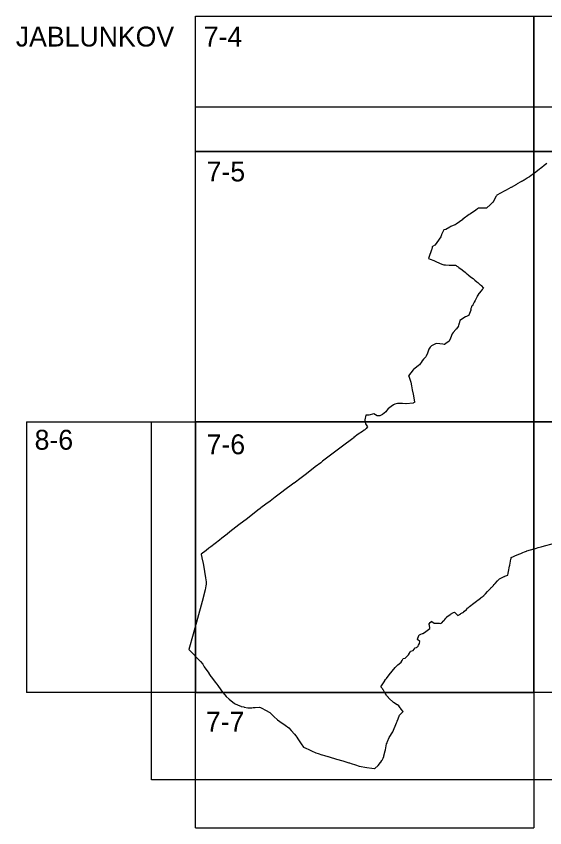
# Model space of a CAD drawing. Extents: x -449577 to -425530, y -1150048 to -1121091.
# Drawn here: x -442174.2 to -441930, y -1122269.2 to -1121894.2 of the extents above; entities that cross this region are included whole.
import ezdxf

# ---------------------------------------------------------------- set-up
doc = ezdxf.new("R2010")
doc.units = 0
for name, color, linetype in [('Vrstva 1', 7, 'Continuous'), ('Vrstva 10', 7, 'Continuous'), ('Vrstva 4', 7, 'Continuous')]:
    doc.layers.add(name, color=color, linetype=linetype)

msp = doc.modelspace()

# ---------------------------------------------------------------- linework, layer by layer
at = {"layer": 'Vrstva 1'}
for points in [[(-441928.97, -1121962.23), (-441930.18, -1121963.19), (-441930.18, -1121963.19), (-441931.33, -1121964.06), (-441931.9, -1121964.49), (-441932.48, -1121964.93), (-441932.64, -1121965.05), (-441934.77, -1121966.69), (-441935.84, -1121967.51), (-441936.31, -1121967.85), (-441937.07, -1121968.36), (-441937.32, -1121968.52), (-441937.91, -1121968.91), (-441937.95, -1121968.94), (-441938.16, -1121969.08), (-441939.07, -1121969.68), (-441939.08, -1121969.68), (-441939.55, -1121969.94), (-441939.7, -1121970.02), (-441939.88, -1121970.12), (-441940.34, -1121970.37), (-441940.52, -1121970.48), (-441940.68, -1121970.57), (-441940.78, -1121970.63), (-441941.02, -1121970.77), (-441942.68, -1121971.71), (-441942.85, -1121971.8), (-441943.08, -1121971.93), (-441945.55, -1121973.33), (-441945.67, -1121973.4), (-441947.78, -1121974.53), (-441948.8, -1121975.08), (-441952.14, -1121976.89), (-441952.31, -1121977.19), (-441952.37, -1121977.3), (-441953.15, -1121978.76), (-441953.83, -1121980.08), (-441953.97, -1121980.21), (-441954.06, -1121980.29), (-441955.2, -1121981.33), (-441956.71, -1121982.71), (-441956.88, -1121982.86), (-441956.88, -1121982.87), (-441957.35, -1121982.88), (-441960.54, -1121982.97), (-441960.55, -1121982.97), (-441960.98, -1121983.26), (-441961.81, -1121983.83), (-441964.28, -1121985.49), (-441964.32, -1121985.51), (-441964.56, -1121985.69), (-441964.83, -1121985.89), (-441967.81, -1121988.02), (-441967.88, -1121988.07), (-441970.88, -1121990.25), (-441971.35, -1121990.59), (-441971.51, -1121990.65), (-441973.45, -1121991.37), (-441973.46, -1121991.37), (-441973.85, -1121991.61), (-441975.73, -1121992.77), (-441976.65, -1121992.98), (-441976.9, -1121993.49), (-441977.66, -1121995), (-441977.67, -1121995.01), (-441977.74, -1121995.27), (-441977.94, -1121996.11), (-441978.77, -1121997.22), (-441980.14, -1121999.17), (-441980.7, -1121999.98), (-441980.73, -1122000), (-441981.89, -1122000.64), (-441981.99, -1122000.7), (-441982.06, -1122001.09), (-441982.21, -1122001.9), (-441982.26, -1122002.09), (-441983.55, -1122005.67), (-441983.72, -1122006.15), (-441983.69, -1122006.14), (-441983.67, -1122006.13), (-441982.99, -1122006.39), (-441981.18, -1122007.05), (-441980.56, -1122007.34), (-441978.27, -1122008.42), (-441978.25, -1122008.42), (-441977.09, -1122008.89), (-441976.62, -1122009.07), (-441976.59, -1122009.08), (-441976.16, -1122009.11), (-441976.02, -1122009.12), (-441975.8, -1122009.14), (-441974.2, -1122009.24), (-441973.16, -1122009.31), (-441972.11, -1122009.28), (-441971.27, -1122009.25), (-441971.26, -1122009.25), (-441970.98, -1122009.4), (-441970.61, -1122009.66), (-441970.06, -1122010.04), (-441969.67, -1122010.32), (-441968.11, -1122011.46), (-441967.94, -1122011.58), (-441966.83, -1122012.5), (-441966.44, -1122012.82), (-441966.26, -1122012.97), (-441965.51, -1122013.58), (-441965.24, -1122013.81), (-441964.64, -1122014.3), (-441964.42, -1122014.48), (-441963.78, -1122014.9), (-441963.03, -1122015.4), (-441963, -1122015.42), (-441962.24, -1122016.1), (-441961.36, -1122016.88), (-441960.92, -1122017.26), (-441959.91, -1122018.15), (-441959.65, -1122018.38), (-441959.6, -1122018.43), (-441959.5, -1122018.53), (-441959.49, -1122018.54), (-441959.4, -1122018.64), (-441959.37, -1122018.67), (-441958.32, -1122019.9), (-441958.33, -1122019.91), (-441958.77, -1122020.4), (-441958.83, -1122020.47), (-441959.4, -1122021.1), (-441960.22, -1122022.16), (-441960.39, -1122022.37), (-441960.95, -1122023.09), (-441961.25, -1122023.62), (-441961.27, -1122023.66), (-441961.28, -1122023.68), (-441961.41, -1122023.96), (-441962.21, -1122025.63), (-441962.52, -1122026.27), (-441963.14, -1122027.56), (-441963.25, -1122027.8), (-441963.26, -1122027.8), (-441963.3, -1122027.83), (-441963.59, -1122028.03), (-441963.67, -1122028.07), (-441963.72, -1122028.17), (-441963.81, -1122028.37), (-441963.9, -1122028.65), (-441964.07, -1122029.21), (-441964.08, -1122029.23), (-441964.2, -1122029.73), (-441964.22, -1122029.8), (-441964.21, -1122029.86), (-441964.2, -1122029.94), (-441964.2, -1122030.01), (-441964.21, -1122030.06), (-441965.09, -1122032.39), (-441965.11, -1122032.44), (-441965.13, -1122032.48), (-441965.14, -1122032.49), (-441965.84, -1122032.79), (-441966.09, -1122032.9), (-441966.56, -1122033.14), (-441969.17, -1122034.83), (-441969.17, -1122034.83), (-441969.54, -1122036.14), (-441969.62, -1122036.4), (-441969.73, -1122036.82), (-441969.79, -1122037.03), (-441969.79, -1122037.04), (-441969.78, -1122037.04), (-441969.61, -1122037.2), (-441969.62, -1122037.21), (-441969.98, -1122037.6), (-441970.78, -1122038.6), (-441970.79, -1122038.61), (-441971, -1122038.86), (-441971, -1122038.87), (-441971.12, -1122039.02), (-441972.28, -1122040.37), (-441972.82, -1122041), (-441973.58, -1122042.95), (-441973.96, -1122043.97), (-441974.09, -1122044.32), (-441975.62, -1122045.42), (-441976.24, -1122045.86), (-441976.42, -1122045.9), (-441976.44, -1122045.9), (-441977.07, -1122045.81), (-441979.91, -1122045.39), (-441980.4, -1122045.63), (-441981.73, -1122046.27), (-441982.27, -1122046.53), (-441982.3, -1122046.56), (-441982.73, -1122046.97), (-441982.9, -1122047.19), (-441983.56, -1122048.04), (-441983.56, -1122048.05), (-441984.23, -1122049.85), (-441984.8, -1122051.35), (-441984.8, -1122051.35), (-441984.94, -1122051.57), (-441985.27, -1122051.94), (-441985.99, -1122052.74), (-441986.69, -1122053.51), (-441986.7, -1122053.53), (-441986.83, -1122053.72), (-441987.9, -1122055.29), (-441988.37, -1122055.67), (-441989.94, -1122056.93), (-441990.61, -1122057.47), (-441990.71, -1122057.55), (-441990.74, -1122057.59), (-441991.86, -1122059.02), (-441993, -1122060.33), (-441992.85, -1122060.5), (-441992.84, -1122060.53), (-441992.84, -1122060.54), (-441991.83, -1122063.3), (-441991.55, -1122064.96), (-441991.23, -1122066.91), (-441990.82, -1122068.87), (-441990.09, -1122072.37), (-441990.05, -1122072.57), (-441990.7, -1122072.91), (-441990.82, -1122072.98), (-441993.99, -1122073.24), (-441994.15, -1122073.24), (-441995.64, -1122073.21), (-441998.03, -1122073.19), (-441999.31, -1122073.46), (-441999.91, -1122073.73), (-442000.89, -1122074.53), (-442002.19, -1122075.4), (-442002.28, -1122075.51), (-442003.44, -1122076.93), (-442004.89, -1122078.27), (-442005.58, -1122078.59), (-442006.18, -1122078.87), (-442007.35, -1122078.8), (-442008.96, -1122077.95), (-442011.2, -1122078.62), (-442012.68, -1122078.59), (-442013.06, -1122080.7), (-442013.07, -1122080.72), (-442013.08, -1122080.81), (-442012.79, -1122082.62), (-442011.82, -1122083.94), (-442011.81, -1122083.96), (-442012.55, -1122084.71), (-442013.16, -1122085.27), (-442013.41, -1122085.5), (-442014.21, -1122086.13), (-442016.14, -1122087.36), (-442016.2, -1122087.4), (-442018.17, -1122088.93), (-442018.23, -1122088.97), (-442018.72, -1122089.35), (-442023.38, -1122092.81), (-442023.41, -1122092.84), (-442028.36, -1122096.6), (-442032.62, -1122099.85), (-442033.5, -1122100.51), (-442036.07, -1122102.45), (-442040.07, -1122105.58), (-442042.51, -1122107.45), (-442045.82, -1122109.98), (-442045.87, -1122110.02), (-442050.66, -1122113.53), (-442050.89, -1122113.71), (-442054.5, -1122116.39), (-442056.89, -1122118.21), (-442058.86, -1122119.69), (-442061.18, -1122121.44), (-442061.41, -1122121.61), (-442062.54, -1122122.5), (-442067.36, -1122126.3), (-442071.25, -1122129.25), (-442075.47, -1122132.5), (-442076.76, -1122133.5), (-442079.15, -1122135.38), (-442080.33, -1122136.3), (-442084.27, -1122139.35), (-442085.2, -1122140.06), (-442086.44, -1122141.02), (-442088.76, -1122142.82), (-442088.76, -1122142.82), (-442088.72, -1122143), (-442088.43, -1122144.38), (-442088.4, -1122144.54), (-442087.87, -1122147.08), (-442087.71, -1122147.81), (-442087.71, -1122147.85), (-442086.78, -1122153.73), (-442086.77, -1122153.76), (-442086.47, -1122155.49), (-442086.47, -1122155.51), (-442086.41, -1122155.88), (-442086.35, -1122156.3), (-442086.38, -1122156.67), (-442086.53, -1122157.4), (-442086.91, -1122159.19), (-442087.2, -1122160.37), (-442087.22, -1122160.42), (-442088.33, -1122164.59), (-442090.43, -1122172.47), (-442092.42, -1122179.69), (-442094.35, -1122186.79), (-442094.36, -1122186.83), (-442089.08, -1122192.43), (-442088.03, -1122193.56), (-442087.27, -1122194.78), (-442085.25, -1122197.84), (-442085.2, -1122197.91), (-442084.19, -1122199.32), (-442084.03, -1122199.53), (-442082.15, -1122202.01), (-442081.58, -1122202.75), (-442081.55, -1122202.79), (-442081.03, -1122203.51), (-442079.65, -1122205.41), (-442079.32, -1122205.86), (-442077.17, -1122208.58), (-442075.77, -1122209.8), (-442073.37, -1122211.78), (-442071.63, -1122212.53), (-442070.44, -1122213.05), (-442070.31, -1122213.1), (-442068.98, -1122213.38), (-442068.84, -1122213.41), (-442067.22, -1122213.74), (-442067.19, -1122213.74), (-442066.23, -1122213.72), (-442065.85, -1122213.72), (-442065.33, -1122213.71), (-442064.65, -1122213.7), (-442063.74, -1122213.66), (-442061.79, -1122213.5), (-442061.34, -1122213.57), (-442060.68, -1122213.92), (-442058.96, -1122214.87), (-442057, -1122215.97), (-442056.48, -1122216.45), (-442055.76, -1122217.13), (-442054.96, -1122217.88), (-442053.64, -1122219.18), (-442053.5, -1122219.28), (-442052.31, -1122220.13), (-442049.9, -1122221.84), (-442048.26, -1122223.02), (-442047.21, -1122224.2), (-442045.57, -1122226.02), (-442044.93, -1122226.73), (-442044.57, -1122227.32), (-442044.11, -1122228.06), (-442043.17, -1122229.53), (-442042.54, -1122230.45), (-442041.5, -1122231.89), (-442040.43, -1122232.4), (-442039.05, -1122233.05), (-442037.74, -1122233.66), (-442035.77, -1122234.55), (-442034.64, -1122234.9), (-442032.92, -1122235.47), (-442032.77, -1122235.52), (-442031.68, -1122235.84), (-442030.26, -1122236.26), (-442030.25, -1122236.26), (-442030.04, -1122236.32), (-442029.98, -1122236.34), (-442029.12, -1122236.6), (-442026.73, -1122237.29), (-442026.61, -1122237.33), (-442026.13, -1122237.47), (-442023.2, -1122238.34), (-442020.51, -1122239.17), (-442020.17, -1122239.27), (-442019.41, -1122239.5), (-442017.4, -1122240.12), (-442015.67, -1122240.67), (-442012.21, -1122241.41)], [(-442012.21, -1122241.41), (-442009.82, -1122241.6), (-442008.62, -1122241.83), (-442008.51, -1122241.74), (-442006.93, -1122240.47), (-442005.9, -1122238.99), (-442005.79, -1122238.84), (-442005.27, -1122238.08), (-442005.16, -1122237.91), (-442005.02, -1122237.68), (-442004.64, -1122237.05), (-442004.37, -1122236.22), (-442004.35, -1122236.15), (-442004.33, -1122236.1), (-442004.3, -1122235.99), (-442004.27, -1122235.9), (-442004.27, -1122235.89), (-442003.64, -1122233.69), (-442003.5, -1122233.17), (-442003.05, -1122230.42), (-442003.05, -1122230.42), (-442002.86, -1122229.98), (-442002.6, -1122229.36), (-442001.81, -1122227.53), (-442000.24, -1122224.88), (-441998.49, -1122220.75), (-441998.17, -1122220.11), (-441998.13, -1122219.98), (-441997.74, -1122218.88), (-441997.15, -1122217.21), (-441995.47, -1122215.5), (-441996.4, -1122214.26), (-441996.46, -1122214.17), (-441996.51, -1122214.11), (-441996.54, -1122214.07), (-441996.61, -1122213.97), (-441996.66, -1122213.89), (-441996.74, -1122213.77), (-441997.1, -1122213.25), (-441997.47, -1122212.79), (-441998.04, -1122212.42), (-441998.14, -1122212.36), (-441999.79, -1122211.29), (-442001.98, -1122209.35), (-442002.11, -1122209.18), (-442002.14, -1122209.14), (-442002.22, -1122209.04), (-442002.56, -1122208.62), (-442002.89, -1122208.21), (-442003.15, -1122207.89), (-442003.63, -1122207.3), (-442003.71, -1122207.2), (-442004.21, -1122206.24), (-442004.5, -1122205.68), (-442004.73, -1122205.25), (-442004.78, -1122205.16), (-442004.82, -1122205.11), (-442005.08, -1122204.82), (-442005.28, -1122204.59), (-442005.54, -1122204.3), (-442005.76, -1122204.05), (-442003.9, -1122201.31), (-442003.81, -1122201.19), (-442003.49, -1122200.74), (-442003.17, -1122200.3), (-442001.84, -1122198.47), (-441999.16, -1122195.21), (-441998.81, -1122194.89), (-441998.1, -1122194.19), (-441997.99, -1122194.1), (-441997.8, -1122193.96), (-441997.2, -1122193.48), (-441996.34, -1122192.64), (-441995.93, -1122191.88), (-441995.46, -1122191.01), (-441994.41, -1122190.77), (-441993.01, -1122189.34), (-441992.47, -1122188.49), (-441992.46, -1122188.48), (-441992.46, -1122188.46), (-441992.25, -1122188.13), (-441992.2, -1122188.05), (-441991.96, -1122187.66), (-441990.8, -1122187.22), (-441989.78, -1122186.04), (-441989.25, -1122185.84), (-441989.13, -1122185.79), (-441988.71, -1122185.63), (-441988.49, -1122185.24), (-441988.44, -1122185.15), (-441988.27, -1122184.85), (-441987.86, -1122184.11), (-441987.66, -1122183.2), (-441987.66, -1122183.18), (-441987.65, -1122183.17), (-441988.7, -1122182.18), (-441988.72, -1122182.17), (-441988.73, -1122182.15), (-441988.78, -1122182.11), (-441988.13, -1122180.31), (-441988.06, -1122180.11), (-441987.9, -1122180.05), (-441987.17, -1122179.76), (-441986.48, -1122179.49), (-441986.36, -1122179.44), (-441985.15, -1122178.73), (-441985.03, -1122178.65), (-441985.03, -1122178.65), (-441985.02, -1122178.64), (-441984.9, -1122178.57), (-441983.04, -1122177.17), (-441983.04, -1122177.13), (-441983.07, -1122176.97), (-441983.14, -1122176.49), (-441983.2, -1122176.14), (-441983.3, -1122175.52), (-441983.32, -1122175.41), (-441983.34, -1122175.28), (-441983.36, -1122175.11), (-441983.39, -1122174.97), (-441982.85, -1122174.41), (-441982.29, -1122173.84), (-441982.25, -1122173.79), (-441982.11, -1122173.89), (-441981.11, -1122174.68), (-441980.43, -1122174.69), (-441980.37, -1122174.69), (-441980.12, -1122174.7), (-441979.96, -1122174.7), (-441978.65, -1122174.72), (-441978.02, -1122174.74), (-441977.75, -1122174.58), (-441977.72, -1122174.56), (-441977.6, -1122174.49), (-441977.46, -1122174.4), (-441977.42, -1122174.37), (-441976.88, -1122173.77), (-441976.77, -1122173.65), (-441976.68, -1122173.55), (-441976.51, -1122173.37), (-441976.43, -1122173.28), (-441976.32, -1122173.16), (-441976.29, -1122173.12), (-441976.26, -1122173.09), (-441976.21, -1122173.03), (-441976.12, -1122172.92), (-441975.72, -1122172.42), (-441975.51, -1122172.16), (-441975.26, -1122171.84), (-441975.15, -1122171.76), (-441973.69, -1122170.69), (-441973.48, -1122170.56), (-441972.12, -1122169.79), (-441971.72, -1122169.56), (-441971.72, -1122169.56), (-441971.58, -1122169.71), (-441970.87, -1122170.42), (-441970.5, -1122170.8), (-441970.32, -1122170.97), (-441970.17, -1122171.12), (-441970.08, -1122171.08), (-441968.8, -1122170.31), (-441968.71, -1122170.26), (-441967.78, -1122169.7), (-441967.74, -1122169.67), (-441967.41, -1122169.38), (-441967.36, -1122169.34), (-441967.19, -1122169.19), (-441967.18, -1122169.18), (-441967.18, -1122169.18), (-441967.14, -1122169.14), (-441967.1, -1122169.1), (-441966.21, -1122168.29), (-441966.19, -1122168.28), (-441965.6, -1122167.74), (-441965.49, -1122167.65), (-441965.38, -1122167.55), (-441965.38, -1122167.55), (-441965.37, -1122167.55), (-441965.37, -1122167.55), (-441965.37, -1122167.54), (-441965.36, -1122167.54), (-441965.35, -1122167.53), (-441965.35, -1122167.53), (-441965.34, -1122167.52), (-441965.34, -1122167.52), (-441965.33, -1122167.52), (-441965.33, -1122167.52), (-441964.75, -1122167.03), (-441962.76, -1122165.35), (-441961.56, -1122164.5), (-441961.44, -1122164.42), (-441961.39, -1122164.38), (-441961.37, -1122164.37), (-441961.32, -1122164.34), (-441960.96, -1122164.07), (-441959.72, -1122163.13), (-441959.54, -1122162.99), (-441959.33, -1122162.83), (-441959.31, -1122162.81), (-441958.43, -1122162.14), (-441958.08, -1122161.87), (-441958.03, -1122161.81), (-441957.94, -1122161.71), (-441957.3, -1122161.03), (-441956.4, -1122160.05), (-441955.04, -1122158.64), (-441954.82, -1122158.41), (-441954.57, -1122158.13), (-441953.73, -1122157.18), (-441953.44, -1122156.86), (-441953.24, -1122156.65), (-441952.95, -1122156.33), (-441951.77, -1122155.14), (-441950.84, -1122154.12), (-441948.78, -1122153.11), (-441948.62, -1122153.06), (-441948.42, -1122152.98), (-441946.98, -1122152.49), (-441946.83, -1122151.62), (-441946.67, -1122150.75), (-441946.25, -1122148.38), (-441946.17, -1122147.91), (-441945.84, -1122146.03), (-441945.64, -1122145.15), (-441945.61, -1122145.03), (-441945.56, -1122144.84), (-441945.55, -1122144.8), (-441945.53, -1122144.73), (-441945.52, -1122144.69), (-441945.51, -1122144.64), (-441945.5, -1122144.6), (-441945.49, -1122144.58), (-441945.43, -1122144.37), (-441944.35, -1122143.83), (-441944.06, -1122143.69), (-441944.04, -1122143.68), (-441943.79, -1122143.55), (-441943.74, -1122143.53), (-441941.97, -1122142.81), (-441941.94, -1122142.8), (-441941.91, -1122142.78), (-441941.11, -1122142.47), (-441940.15, -1122142.07), (-441939.34, -1122141.73), (-441938.4, -1122141.34), (-441938.32, -1122141.31), (-441937.71, -1122141.07), (-441937.86, -1122141.23), (-441937.62, -1122141.14), (-441937.13, -1122140.94), (-441936.6, -1122140.78), (-441934.9, -1122140.26), (-441934.31, -1122140.09), (-441933.86, -1122139.97), (-441932.97, -1122139.72), (-441931.66, -1122139.34), (-441930.12, -1122138.88), (-441926.58, -1122138.01)]]:
    msp.add_lwpolyline(points, dxfattribs=at)
at = {"layer": 'Vrstva 10'}
msp.add_lwpolyline([(-441778.82, -1121936.02), (-441778.82, -1122247), (-442111.69, -1122247), (-442111.69, -1122081.7), (-442091.32, -1122081.7), (-442091.32, -1121956.7), (-442091.32, -1121936.02), (-441778.82, -1121936.02)], dxfattribs=at)
at = {"layer": 'Vrstva 4'}
for p, q in [((-442091.32, -1121894.2), (-441778.82, -1121894.2)), ((-442169.45, -1122081.7), (-442169.45, -1122206.7)), ((-442091.32, -1122269.2), (-441935.07, -1122269.2))]:
    msp.add_line(p, q, dxfattribs=at)
for points in [[(-441935.07, -1121894.2), (-441935.07, -1121956.7), (-442091.32, -1121956.7), (-442091.32, -1121894.2)], [(-441778.82, -1121894.2), (-441778.82, -1121956.7), (-441935.07, -1121956.7), (-441935.07, -1121894.2)], [(-442169.45, -1122081.7), (-442091.32, -1122081.7), (-442091.32, -1122206.7), (-442169.45, -1122206.7)], [(-442091.32, -1122269.2), (-442091.32, -1122206.7), (-441935.07, -1122206.7), (-441935.07, -1122269.2)]]:
    msp.add_lwpolyline(points, dxfattribs=at)
for points in [[(-441935.07, -1121956.7), (-441935.07, -1122081.7), (-442091.32, -1122081.7), (-442091.32, -1121956.7)], [(-441778.82, -1121956.7), (-441778.82, -1122081.7), (-441935.07, -1122081.7), (-441935.07, -1121956.7)], [(-441935.07, -1122081.7), (-441935.07, -1122206.7), (-442091.32, -1122206.7), (-442091.32, -1122081.7)], [(-441778.82, -1122081.7), (-441778.82, -1122206.7), (-441935.07, -1122206.7), (-441935.07, -1122081.7)]]:
    msp.add_lwpolyline(points, close=True, dxfattribs=at)

# ---------------------------------------------------------------- texts
at = {"layer": 'Vrstva 1'}
for s, p in [('JABLUNKOV', (-442174.36, -1121908.2)), ('7-4', (-442087.51, -1121908.2)), ('7-5', (-442086.2, -1121970.54)), ('8-6', (-442165.67, -1122094.51)), ('7-6', (-442086.2, -1122096.61)), ('7-7', (-442086.56, -1122224.78))]:
    msp.add_text(s, height=9.2, dxfattribs=at).set_placement(p)

doc.saveas('drawing.dxf')
